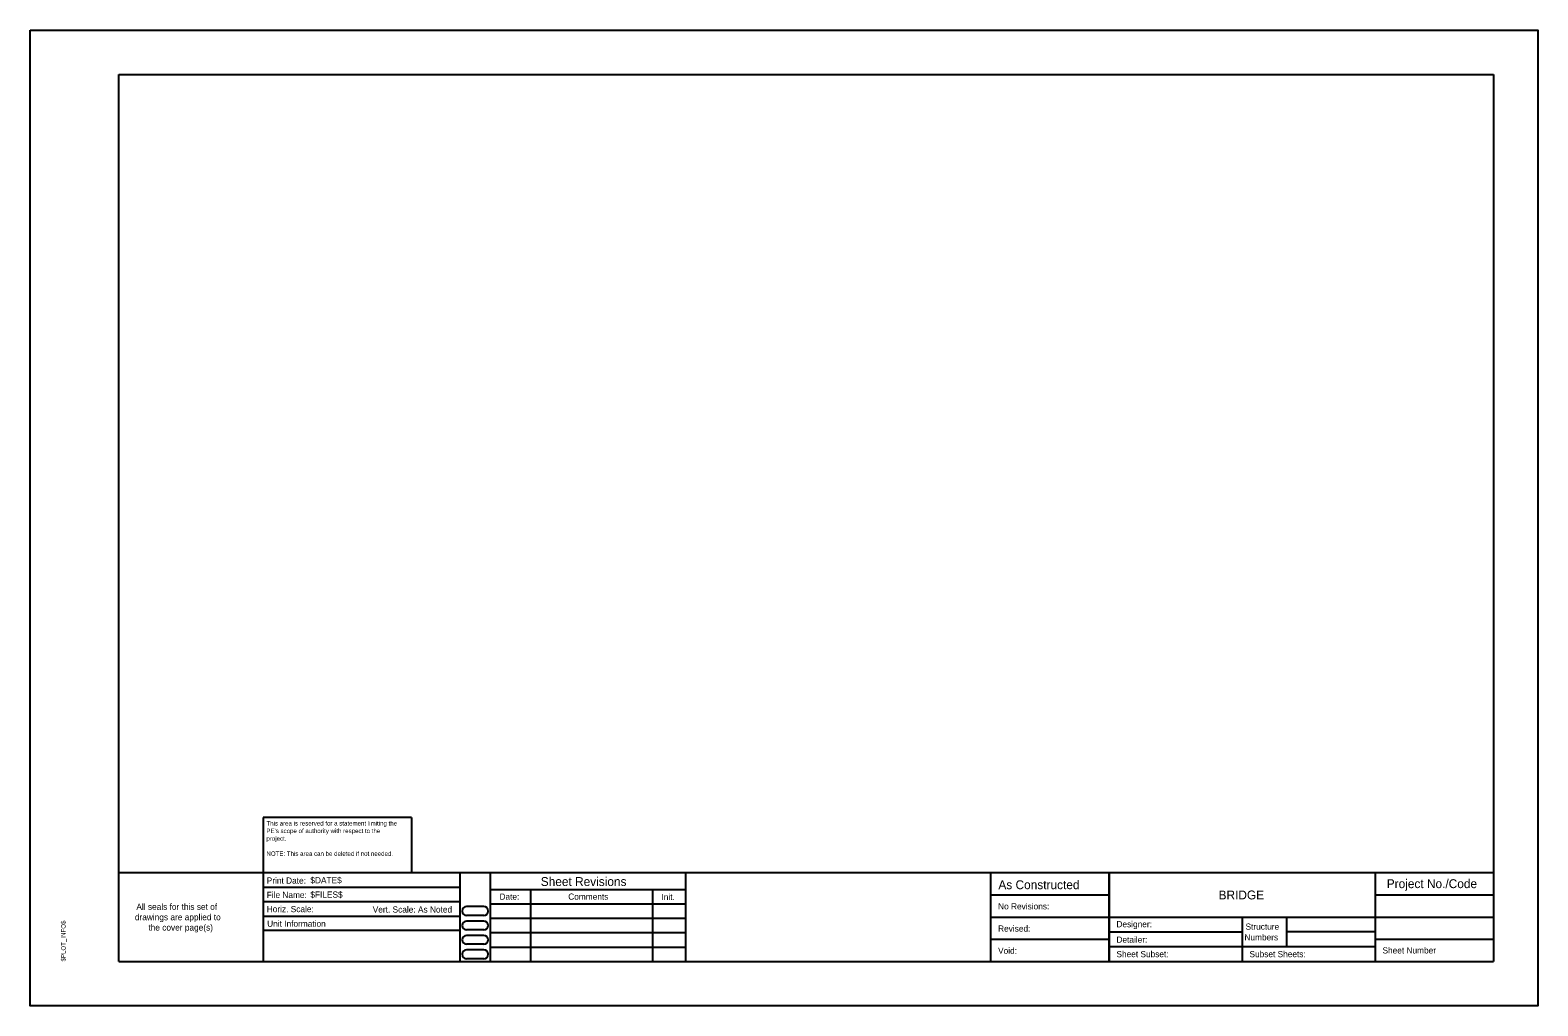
# Model space of a CAD drawing. Extents: x 0 to 1.42, y 0 to 0.92.
import ezdxf

# ---------------------------------------------------------------- set-up
doc = ezdxf.new("R2010")
doc.units = 0
for name, color, linetype in [('DRAFT_Information-No Plot', 7, 'Continuous'), ('SHEET_Lines', 7, 'Continuous'), ('SHEET_Plot Boundary', 7, 'Continuous'), ('SHEET_Text-Border Info', 7, 'Continuous'), ('SHEET_Text-Titles', 7, 'Continuous')]:
    doc.layers.add(name, color=color, linetype=linetype)

msp = doc.modelspace()

# ---------------------------------------------------------------- linework, layer by layer
at = {"layer": 'DRAFT_Information-No Plot'}
for p, q in [((0.3583, 0.1771), (0.2188, 0.1771)), ((0.2188, 0.1771), (0.2188, 0.125)), ((0.3583, 0.1771), (0.3583, 0.125))]:
    msp.add_line(p, q, dxfattribs=at)
at = {"layer": 'SHEET_Lines'}
for p, q in [((0.0833, 0.875), (1.375, 0.875)), ((0.0833, 0.0417), (0.0833, 0.875)), ((1.375, 0.875), (1.375, 0.0417)), ((1.375, 0.125), (0.0833, 0.125)), ((0.2188, 0.125), (0.2188, 0.0417)), ((0.4042, 0.0417), (0.4042, 0.125)), ((0.4324, 0.0417), (0.4324, 0.125)), ((0.616, 0.0417), (0.616, 0.125)), ((0.9028, 0.0417), (0.9028, 0.125)), ((1.0139, 0.125), (1.0139, 0.0417)), ((1.0139, 0.0417), (1.0139, 0.125)), ((1.2639, 0.125), (1.2639, 0.0417)), ((0.2188, 0.1115), (0.4042, 0.1115)), ((0.4324, 0.1094), (0.616, 0.1094)), ((0.4706, 0.0417), (0.4706, 0.1094)), ((0.5852, 0.0417), (0.5852, 0.1094)), ((0.9028, 0.1042), (1.0139, 0.1042)), ((1.2639, 0.1042), (1.375, 0.1042)), ((0.2188, 0.098), (0.4042, 0.098)), ((0.4264, 0.0932), (0.41, 0.0932)), ((0.4324, 0.0958), (0.616, 0.0958)), ((0.2188, 0.0844), (0.4042, 0.0844)), ((0.4042, 0.0709), (0.2188, 0.0709)), ((0.4264, 0.085), (0.41, 0.085)), ((0.4264, 0.0796), (0.41, 0.0796)), ((0.4264, 0.0714), (0.41, 0.0714)), ((0.4324, 0.0823), (0.616, 0.0823)), ((0.9028, 0.0833), (1.375, 0.0833)), ((1.1389, 0.0833), (1.1389, 0.0417)), ((1.1806, 0.0833), (1.1806, 0.0556)), ((0.4264, 0.0661), (0.41, 0.0661)), ((0.4264, 0.0579), (0.41, 0.0579)), ((0.4324, 0.0688), (0.616, 0.0688)), ((0.9028, 0.0625), (1.0139, 0.0625)), ((1.0139, 0.0694), (1.1389, 0.0694)), ((1.2639, 0.0694), (1.1806, 0.0694)), ((1.2639, 0.0625), (1.375, 0.0625)), ((0.4264, 0.0525), (0.41, 0.0525)), ((0.4264, 0.0443), (0.41, 0.0443)), ((0.4324, 0.0552), (0.616, 0.0552)), ((1.0139, 0.0556), (1.2639, 0.0556)), ((0.0833, 0.0417), (1.375, 0.0417))]:
    msp.add_line(p, q, dxfattribs=at)
for centre, start, end in [((0.41, 0.0891), 90, 270), ((0.4264, 0.0891), 270, 90), ((0.41, 0.0755), 90, 270), ((0.4264, 0.0755), 270, 90), ((0.41, 0.062), 90, 270), ((0.4264, 0.062), 270, 90), ((0.41, 0.0484), 90, 270), ((0.4264, 0.0484), 270, 90)]:
    msp.add_arc(centre, 0.00409, start, end, dxfattribs=at)
at = {"layer": 'SHEET_Plot Boundary'}
msp.add_lwpolyline([(0, 0.9167), (1.4167, 0.9167), (1.4167, 0), (0, 0)], close=True, dxfattribs=at)

# ---------------------------------------------------------------- texts
at = {"layer": 'DRAFT_Information-No Plot'}
for s, height, p in [('This area is reserved for a statement limiting the', 0.004167, (0.222, 0.1694)), ('project.', 0.00417, (0.222, 0.1551)), ("PE's scope of authority with respect to the ", 0.004167, (0.222, 0.1623)), ('NOTE: This area can be deleted if not needed.', 0.004167, (0.222, 0.1409))]:
    msp.add_text(s, height=height, dxfattribs=at).set_placement(p)
at = {"layer": 'SHEET_Text-Border Info'}
for s, height, p in [('Print Date:', 0.005833, (0.2223, 0.1148)), ('$DATE$', 0.00583, (0.2633, 0.1151)), ('File Name:', 0.00583, (0.2223, 0.1013)), ('$FILES$', 0.00583, (0.2633, 0.1016)), ('Date:', 0.00583, (0.441, 0.0997)), ('Comments', 0.00583, (0.5056, 0.0997)), ('Init.', 0.00583, (0.5932, 0.0994)), ('drawings are applied to', 0.005833, (0.0984, 0.0804)), ('All seals for this set of', 0.005833, (0.0998, 0.0902)), ('Horiz. Scale:', 0.005833, (0.2223, 0.088)), ('Vert. Scale: As Noted', 0.005833, (0.3219, 0.0876)), ('No Revisions:', 0.005833, (0.9095, 0.0906)), ('the cover page(s)', 0.005833, (0.1111, 0.0707)), ('Unit Information', 0.005833, (0.2227, 0.0743)), ('Revised:', 0.00583, (0.9095, 0.0697)), ('Designer:', 0.00583, (1.0207, 0.0738)), ('Structure', 0.00583, (1.142, 0.0715)), ('Detailer:', 0.00583, (1.0207, 0.0593)), ('Numbers', 0.00583, (1.141, 0.0615)), ('Void:', 0.00583, (0.9095, 0.0489)), ('Sheet Subset:', 0.005833, (1.0207, 0.0457)), ('Subset Sheets:', 0.005833, (1.1457, 0.0457)), ('Sheet Number', 0.005833, (1.2707, 0.0492))]:
    msp.add_text(s, height=height, dxfattribs=at).set_placement(p)
msp.add_text('$PLOT_INFO$', height=0.004167, rotation=90, dxfattribs=at).set_placement((0.0333, 0.0417))
at = {"layer": 'SHEET_Text-Titles'}
for s, height, p in [('Sheet Revisions', 0.008333, (0.4798, 0.1126)), ('As Constructed', 0.008333, (0.9098, 0.1096)), ('Project No./Code', 0.008333, (1.2747, 0.1106)), ('BRIDGE', 0.00833, (1.1167, 0.1))]:
    msp.add_text(s, height=height, dxfattribs=at).set_placement(p)

doc.saveas('drawing.dxf')
